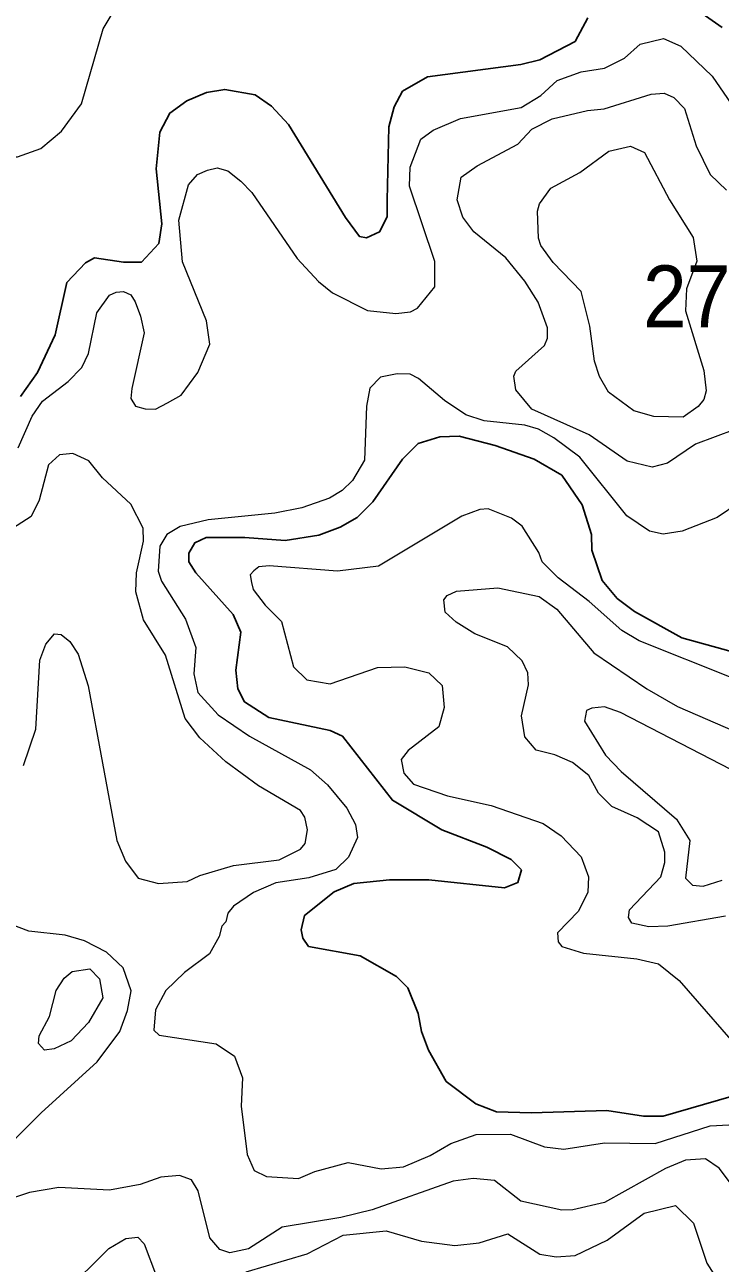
# Model space of a CAD drawing. Extents: x 673.6 to 698.9, y 7012 to 7040.1.
# Drawn here: x 678.986 to 679.882, y 7017.545 to 7019.142 of the extents above; entities that cross this region are included whole.
import ezdxf

# ---------------------------------------------------------------- set-up
doc = ezdxf.new("R2010")
doc.units = 0
doc.header["$LTSCALE"] = 0.032
doc.layers.add('1', color=7, linetype='Continuous', lineweight=25)
doc.layers.add('2', color=7, linetype='Continuous', lineweight=13)
doc.layers.add('21', color=7, linetype='Continuous')

msp = doc.modelspace()

# ---------------------------------------------------------------- linework, layer by layer
at = {"layer": '1'}
for points in [[(679.8848, 7019.1388), (679.8261, 7019.1802)], [(679.7117, 7019.1513), (679.6953, 7019.1208), (679.6501, 7019.0972), (679.6254, 7019.0908), (679.5051, 7019.0752), (679.4729, 7019.0565), (679.4621, 7019.0362), (679.4554, 7019.0108), (679.453, 7018.916), (679.4531, 7018.8944), (679.4434, 7018.875), (679.4263, 7018.8676), (679.4174, 7018.8694), (679.3993, 7018.8937), (679.3261, 7019.0136), (679.3042, 7019.0374), (679.2828, 7019.0517), (679.2438, 7019.0588), (679.2204, 7019.0547), (679.1949, 7019.0443), (679.1728, 7019.0283), (679.1602, 7019.0037), (679.1555, 7018.9563), (679.1627, 7018.8856), (679.1586, 7018.8601), (679.1364, 7018.8363), (679.1131, 7018.8362)], [(679.1131, 7018.8362), (679.0758, 7018.8417), (679.0643, 7018.8353), (679.0402, 7018.8098), (679.0251, 7018.7425), (679.0024, 7018.6937)], [(679.0024, 7018.6937), (678.9803, 7018.6628)], [(679.3954, 7018.2247), (679.3796, 7018.2324), (679.3006, 7018.2488), (679.2691, 7018.269), (679.2608, 7018.2861), (679.2582, 7018.3101), (679.2645, 7018.3591), (679.2548, 7018.3817), (679.2064, 7018.4356), (679.1976, 7018.4496), (679.1974, 7018.461), (679.2051, 7018.4744), (679.22, 7018.4811), (679.2695, 7018.4812), (679.3216, 7018.4771), (679.3649, 7018.484), (679.3925, 7018.4942), (679.4143, 7018.5067), (679.4348, 7018.5271), (679.4727, 7018.5822), (679.493, 7018.6024), (679.5211, 7018.611), (679.5458, 7018.6118), (679.5925, 7018.5998), (679.6427, 7018.5822), (679.6781, 7018.5616), (679.7044, 7018.523), (679.7166, 7018.4848), (679.7168, 7018.4646), (679.7301, 7018.4258), (679.7495, 7018.4025), (679.7721, 7018.3856), (679.8331, 7018.3515), (679.9061, 7018.3316)], [(679.6261, 7018.0524), (679.613, 7018.0658), (679.5815, 7018.0819), (679.5236, 7018.1043), (679.4599, 7018.1423), (679.3954, 7018.2247)], [(679.8967, 7017.7603), (679.8087, 7017.7351), (679.7837, 7017.7351), (679.7364, 7017.7424), (679.6393, 7017.7391), (679.5939, 7017.7407), (679.5673, 7017.7508), (679.5291, 7017.7797), (679.5062, 7017.82), (679.4973, 7017.8443), (679.4932, 7017.8673), (679.4797, 7017.9004), (679.4652, 7017.9149), (679.4184, 7017.9417), (679.3519, 7017.9538), (679.3445, 7017.9643), (679.3421, 7017.975), (679.3466, 7017.9937), (679.3849, 7018.0241), (679.4103, 7018.0349), (679.4561, 7018.0398), (679.5067, 7018.0398), (679.6045, 7018.0293), (679.6216, 7018.0363), (679.6261, 7018.0524)]]:
    msp.add_lwpolyline(points, dxfattribs=at)
at = {"layer": '2'}
for points in [[(678.9236, 7019.184), (678.9612, 7019.1397), (678.9722, 7019.116), (678.9722, 7019.095), (678.9526, 7018.9992), (678.9532, 7018.9832), (678.966, 7018.9721), (678.9768, 7018.9718), (679.0068, 7018.9827), (679.0333, 7019.0049), (679.0593, 7019.0403), (679.087, 7019.137), (679.1051, 7019.167)], [(678.9773, 7018.5967), (678.9957, 7018.6376), (679.0088, 7018.6568), (679.0421, 7018.6823), (679.0597, 7018.7004), (679.0682, 7018.7183), (679.0789, 7018.7706), (679.0951, 7018.7934), (679.1038, 7018.7976), (679.1134, 7018.7982), (679.1225, 7018.7938), (679.1283, 7018.7849), (679.1351, 7018.7663), (679.1398, 7018.7449), (679.1239, 7018.6732), (679.1225, 7018.6605), (679.1288, 7018.6505), (679.1411, 7018.6471), (679.1546, 7018.6464), (679.1701, 7018.6546), (679.1875, 7018.6645), (679.2092, 7018.6938), (679.2244, 7018.7305), (679.2201, 7018.7604), (679.1893, 7018.8367), (679.1844, 7018.8902), (679.1971, 7018.936), (679.2087, 7018.9491), (679.2215, 7018.9547), (679.234, 7018.9577), (679.2476, 7018.9539), (679.2647, 7018.9405), (679.2785, 7018.926), (679.3373, 7018.8408), (679.3647, 7018.811), (679.3825, 7018.7966), (679.4278, 7018.7737), (679.4641, 7018.7697), (679.4833, 7018.7721), (679.4924, 7018.7768), (679.5145, 7018.8042), (679.5145, 7018.837), (679.4818, 7018.934), (679.4826, 7018.9586), (679.4965, 7018.9946), (679.5123, 7019.0063), (679.5476, 7019.0214), (679.6258, 7019.0357), (679.6511, 7019.0511), (679.6724, 7019.0703), (679.7032, 7019.0817), (679.7334, 7019.0861), (679.7591, 7019.099), (679.7792, 7019.1171), (679.8095, 7019.1245), (679.8317, 7019.1147), (679.872, 7019.076), (679.9313, 7018.9895)], [(679.9011, 7018.6202), (679.8504, 7018.6014), (679.8144, 7018.577), (679.7946, 7018.5716), (679.7625, 7018.5794), (679.7137, 7018.6133), (679.6398, 7018.6464), (679.6189, 7018.6713), (679.6164, 7018.6891), (679.619, 7018.6956), (679.656, 7018.7288), (679.66, 7018.7383), (679.66, 7018.7515), (679.6477, 7018.7844), (679.6306, 7018.8115), (679.606, 7018.8416), (679.5649, 7018.8753), (679.5508, 7018.8941), (679.5434, 7018.9165), (679.5487, 7018.9455), (679.5691, 7018.9604), (679.6215, 7018.9883), (679.6397, 7019.0075), (679.666, 7019.0211), (679.7112, 7019.0316), (679.7329, 7019.0336), (679.7933, 7019.0529), (679.8101, 7019.0539), (679.8225, 7019.0483), (679.8366, 7019.0343), (679.8516, 7018.9863), (679.8697, 7018.9493), (679.8905, 7018.9289)], [(679.9066, 7018.5256), (679.8784, 7018.5069), (679.8334, 7018.4894), (679.8088, 7018.4853), (679.7914, 7018.4892), (679.7622, 7018.5088), (679.7014, 7018.5845), (679.6681, 7018.6097), (679.6481, 7018.6207), (679.6306, 7018.6259), (679.5783, 7018.6316), (679.5547, 7018.6394), (679.5271, 7018.6576), (679.4937, 7018.6859), (679.4826, 7018.6916), (679.4662, 7018.6923), (679.4446, 7018.688), (679.4307, 7018.6737), (679.4267, 7018.6503), (679.4241, 7018.581), (679.4083, 7018.5545), (679.3952, 7018.5416), (679.3788, 7018.5316), (679.3431, 7018.5192), (679.3082, 7018.5124), (679.2225, 7018.5038), (679.1865, 7018.4954), (679.1692, 7018.485), (679.1603, 7018.4701), (679.158, 7018.4377), (679.1621, 7018.4248), (679.1932, 7018.3759), (679.2063, 7018.3393), (679.204, 7018.3054), (679.2089, 7018.281), (679.2351, 7018.2524), (679.2756, 7018.2251), (679.3545, 7018.1816), (679.3763, 7018.1623), (679.4011, 7018.1319), (679.4124, 7018.1109), (679.415, 7018.0942), (679.4032, 7018.0688), (679.3868, 7018.0529), (679.3521, 7018.0424), (679.3098, 7018.036), (679.2808, 7018.0232), (679.2552, 7018.0055), (679.2478, 7017.9967), (679.2452, 7017.9853), (679.2398, 7017.9799), (679.2367, 7017.9668), (679.2241, 7017.9442), (679.1919, 7017.9203), (679.1679, 7017.897), (679.1545, 7017.8719), (679.1524, 7017.8458), (679.1591, 7017.8394), (679.2329, 7017.828), (679.2565, 7017.8122), (679.2665, 7017.7844), (679.2648, 7017.7478), (679.2727, 7017.6856), (679.2818, 7017.6647), (679.2974, 7017.657), (679.3388, 7017.6545), (679.3601, 7017.6635), (679.4028, 7017.675), (679.4452, 7017.6669), (679.474, 7017.6698), (679.5086, 7017.6844), (679.5351, 7017.6996), (679.5678, 7017.7112), (679.6122, 7017.7118), (679.6559, 7017.6955), (679.6808, 7017.6923), (679.7331, 7017.7004), (679.7986, 7017.6996), (679.8695, 7017.7226), (679.9174, 7017.7251)], [(678.9845, 7018.187), (679.0001, 7018.2338), (679.0054, 7018.3228), (679.0132, 7018.3436), (679.0244, 7018.3569), (679.033, 7018.3561), (679.0441, 7018.3468), (679.0549, 7018.3306), (679.0675, 7018.29), (679.1045, 7018.0902), (679.1157, 7018.0639), (679.1322, 7018.042), (679.1582, 7018.035), (679.1955, 7018.0374), (679.2115, 7018.0453), (679.2552, 7018.058), (679.3141, 7018.0656), (679.3416, 7018.079), (679.3475, 7018.0865), (679.3503, 7018.1041), (679.3469, 7018.1204), (679.3415, 7018.129), (679.2874, 7018.1608), (679.2453, 7018.1918), (679.2116, 7018.2229), (679.1926, 7018.2477), (679.1676, 7018.3295), (679.1391, 7018.375), (679.1292, 7018.411), (679.1299, 7018.4353), (679.1389, 7018.4763), (679.1388, 7018.4929), (679.1226, 7018.5239), (679.0862, 7018.5578), (679.0687, 7018.5801), (679.0481, 7018.5895), (679.0309, 7018.5875), (679.0166, 7018.5746), (679.0046, 7018.5292), (678.9944, 7018.5083), (678.9643, 7018.4887)], [(679.8985, 7018.2998), (679.7779, 7018.3479), (679.7558, 7018.3612), (679.7137, 7018.3987), (679.6735, 7018.4289), (679.6529, 7018.4498), (679.6487, 7018.4618), (679.6271, 7018.4958), (679.6132, 7018.5061), (679.5835, 7018.518), (679.5725, 7018.517), (679.5495, 7018.5084), (679.4419, 7018.4441)], [(679.4419, 7018.4441), (679.3893, 7018.4377), (679.3012, 7018.4446), (679.2878, 7018.4431), (679.2813, 7018.438), (679.2764, 7018.4329)], [(679.2764, 7018.4329), (679.2781, 7018.423), (679.2804, 7018.4141), (679.296, 7018.394), (679.3171, 7018.3727), (679.3324, 7018.3141), (679.3495, 7018.2975), (679.3795, 7018.2922), (679.4406, 7018.3135), (679.4759, 7018.3143), (679.5069, 7018.3067), (679.5239, 7018.2901), (679.5268, 7018.2618), (679.5197, 7018.237), (679.48, 7018.2066), (679.4712, 7018.1947), (679.4747, 7018.1774), (679.4871, 7018.1632), (679.5307, 7018.148), (679.5873, 7018.1355), (679.6542, 7018.1122), (679.6776, 7018.0963), (679.7034, 7018.0694), (679.7127, 7018.0436), (679.7118, 7018.0238), (679.6999, 7017.9993), (679.6725, 7017.9712), (679.6737, 7017.9596), (679.6782, 7017.9537), (679.7064, 7017.9451), (679.775, 7017.9378), (679.8029, 7017.9313), (679.8297, 7017.9097), (679.9193, 7017.8068)], [(679.6304, 7018.2242), (679.6264, 7018.2511), (679.6353, 7018.2913), (679.6345, 7018.3066), (679.6272, 7018.3222), (679.6081, 7018.3399), (679.5662, 7018.3567), (679.5421, 7018.3718), (679.528, 7018.3849), (679.5261, 7018.4007), (679.5305, 7018.4064), (679.5425, 7018.412), (679.5959, 7018.4161), (679.649, 7018.4048), (679.6718, 7018.3888), (679.7194, 7018.3322), (679.7879, 7018.2858), (679.8275, 7018.2631), (679.9017, 7018.2308)], [(679.8962, 7018.1819), (679.7538, 7018.2554), (679.7331, 7018.2629), (679.7169, 7018.2609), (679.7101, 7018.2582), (679.7076, 7018.2442), (679.7346, 7018.2004), (679.7548, 7018.1793), (679.8259, 7018.118), (679.8432, 7018.0904), (679.8376, 7018.0417), (679.8469, 7018.0328), (679.8603, 7018.0317), (679.885, 7018.0392)], [(679.7256, 7018.1516), (679.7131, 7018.174), (679.692, 7018.191), (679.6693, 7018.2008), (679.6451, 7018.2068), (679.6304, 7018.2242)], [(679.8893, 7017.993), (679.8149, 7017.9799), (679.7904, 7017.9791), (679.7685, 7017.9836), (679.7643, 7017.9911), (679.7654, 7018.0011), (679.8058, 7018.0436), (679.8112, 7018.0619), (679.8111, 7018.0752), (679.8028, 7018.1015), (679.7753, 7018.1198), (679.7429, 7018.1344), (679.7256, 7018.1516)], [(678.9412, 7017.6736), (679.007, 7017.7394), (679.0792, 7017.8051), (679.1084, 7017.844), (679.1185, 7017.871), (679.1233, 7017.8966), (679.113, 7017.9261), (679.0912, 7017.9462), (679.063, 7017.9608), (679.0379, 7017.9683), (678.9911, 7017.9734), (678.9514, 7017.9885)], [(679.9317, 7017.6004), (679.8812, 7017.6677), (679.8634, 7017.6799), (679.8378, 7017.678), (679.812, 7017.6676), (679.7334, 7017.6234), (679.6924, 7017.6141), (679.6784, 7017.6137), (679.6255, 7017.6253), (679.5915, 7017.6519), (679.5638, 7017.6544), (679.538, 7017.6512), (679.4337, 7017.6142), (679.3933, 7017.6041), (679.3177, 7017.5919), (679.2742, 7017.564), (679.2503, 7017.5585), (679.2373, 7017.5629), (679.2245, 7017.5782), (679.2097, 7017.6388), (679.2009, 7017.653), (679.1855, 7017.6585), (679.1612, 7017.6561), (679.1346, 7017.647), (679.0954, 7017.6397), (679.0301, 7017.643), (678.9919, 7017.6363), (678.9522, 7017.6232)], [(679.2714, 7017.5344), (679.35, 7017.5574), (679.3962, 7017.5813), (679.4518, 7017.5871), (679.4972, 7017.5738), (679.5405, 7017.5682), (679.5718, 7017.5714), (679.6087, 7017.583), (679.6501, 7017.5572), (679.6711, 7017.5534), (679.6953, 7017.5551), (679.7367, 7017.5749), (679.7842, 7017.6099), (679.8248, 7017.6198), (679.8481, 7017.5968), (679.8654, 7017.5453), (679.8823, 7017.5185)], [(679.0365, 7017.5068), (679.0944, 7017.5645), (679.1164, 7017.5774), (679.1318, 7017.5788), (679.1399, 7017.5703), (679.1558, 7017.5281)]]:
    msp.add_lwpolyline(points, dxfattribs=at)
for points in [[(679.8376, 7018.7735), (679.8615, 7018.6966), (679.8642, 7018.6701), (679.8614, 7018.659), (679.8539, 7018.6498), (679.8347, 7018.6364), (679.7968, 7018.637), (679.7709, 7018.6443), (679.7383, 7018.6683), (679.7267, 7018.6887), (679.7205, 7018.7085), (679.7142, 7018.7535), (679.703, 7018.7984), (679.6671, 7018.8357), (679.6514, 7018.8576), (679.6481, 7018.8671), (679.6467, 7018.902), (679.6496, 7018.9112), (679.6642, 7018.9313), (679.7014, 7018.9518), (679.7387, 7018.9794), (679.7669, 7018.9856), (679.7849, 7018.9773), (679.817, 7018.9164), (679.8476, 7018.8677), (679.8522, 7018.8373), (679.839, 7018.8017)], [(679.068, 7017.8555), (679.0457, 7017.8319), (679.024, 7017.8216), (679.0114, 7017.82), (679.0035, 7017.8286), (679.0047, 7017.8387), (679.0177, 7017.8636), (679.0265, 7017.8969), (679.0367, 7017.9128), (679.0473, 7017.9216), (679.0697, 7017.9251), (679.0822, 7017.9122), (679.0865, 7017.8876)]]:
    msp.add_lwpolyline(points, close=True, dxfattribs=at)

# ---------------------------------------------------------------- texts
at = {"layer": '21', "width": 0.95}
msp.add_text('279', height=0.08, dxfattribs=at).set_placement((679.7828, 7018.7519))

doc.saveas('drawing.dxf')
